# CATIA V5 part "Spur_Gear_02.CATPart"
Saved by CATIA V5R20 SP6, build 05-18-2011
Part number: Spur_Gear_02
Bounding box of the stored display mesh (mm): x 21 to 25, y 3.763 to 18.937, z -14.232 to 0.888
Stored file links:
  E:\#01 CATIA Lecture Materials\#06 DMU\#16 DMU Page01 KIN EX16\Spur_Gear_02.CATPart
  E:\#01 CATIA Lecture Materials\#06 DMU\#10 Kinematics Joints\#07 Internal Gear Assay\spur_gear_0.8x16.CATPart
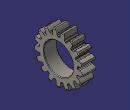
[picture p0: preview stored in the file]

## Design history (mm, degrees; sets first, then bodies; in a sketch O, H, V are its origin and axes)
Set1
  Sketch1, origin (0, 0, 0), H (0, 1, 0), V (0, 0, 1), geometry linked from another document
Body1 (main body)
Body2
  Solid1: solid without history
  Translate1: Direction Sketch1, Length 3.15, ToTransfor Solid1
  Sketch2 on face of Solid1, origin (25.5, 8.1428, -4.549), H (0, 1, 0), V (0, 0, 1)
    point P1 (3.2108, -2.0856)
    reference projected circle E1 centre (3.2108, -2.0856) radius 4.5 from edge [face of Solid1 | face of Solid1]
    concentricity: E1 P1
  Hole1: placed by Sketch2, at (25.5, 11.3536, -6.6346) direction (-1, 0, 0), diameter 9, through (limit type 6)
  Chamfer1: length 0.15, angle 45, on face of Hole1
